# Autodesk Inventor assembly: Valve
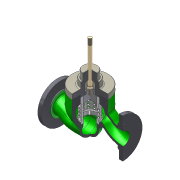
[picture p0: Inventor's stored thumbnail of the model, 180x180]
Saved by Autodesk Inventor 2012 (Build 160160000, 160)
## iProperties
Company: Autodesk
RuleStatus: InUse
Created: 2002-11
Part Number: Valve
Document SubType Name: Assembly
Designer: Lieven Grauls
Project: Valve Techcamp 2008
Mass: 9596.69 g
Surface Area: 3914.24 cm^2
Volume: 1891.29 cm^3
Density: 5.07414 g/cm^3
Control State: 0
Master: False
Checked Out: False
Shininess: 64.0
Length Units: 11269
Angle Units: 11279
Time Units: 11290
Mass Units: 11283
Length Display Precision: 3
Angle Display Precision: 2
Compacted: True
Density: 0.0
Volumn: 0.0
Area: 0.0
PropertySet Name: Model Information
Author: Lieven Grauls
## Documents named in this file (5)
- C:\CMU\Week 14\Problem set\Valve\Assemblies\Valve.iam
- C:\CMU\Week 14\Problem set\Valve\Parts\guide_02.ipt
- C:\CMU\Week 14\Problem set\Valve\Assemblies\plug_02.iam
- C:\CMU\Week 14\Problem set\Valve\Parts\lit_mch_02.ipt
- C:\CMU\Week 14\Problem set\Valve\Parts\02_area_loft_Machined.ipt
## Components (4 placed, 4 different names)
1. 02_area_loft_Machined:1 — Insert:1, Insert:2, Flush:4, Insert:3, Angle:1
2. guide_02:1 — Insert:1, Insert:2, Flush:2, Mate:1, Angle:1
3. plug_02:1 [sub-assembly] — Flush:2, Mate:1
4. lit_mch_02:1 — Flush:4, Insert:3
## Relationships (7: Insert 3, Flush 2, Mate 1, Angle 1)
- Insert:1: 02_area_loft_Machined:1 ↔ guide_02:1
- Insert:2: 02_area_loft_Machined:1 ↔ guide_02:1
- Flush:2: guide_02:1 ↔ plug_02:1
- Mate:1: guide_02:1 ↔ plug_02:1
- Flush:4: 02_area_loft_Machined:1 ↔ lit_mch_02:1
- Insert:3: 02_area_loft_Machined:1 ↔ lit_mch_02:1
- Angle:1: 02_area_loft_Machined:1 ↔ guide_02:1
## Named parameters: PlugPosition = 0
